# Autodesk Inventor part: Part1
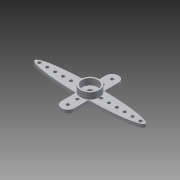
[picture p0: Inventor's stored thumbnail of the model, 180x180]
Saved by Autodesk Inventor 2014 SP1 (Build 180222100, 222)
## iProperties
Created: 2017-05
Part Number: Part1
Material: PVC-Piping
Document SubType Name: Modeling
Designer: L.Đ.P
Density: 1.4 g/cm^3
Appearance: Smooth - White
Author: L.Đ.P
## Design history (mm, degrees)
sketch "Sketch1" dims "d0" = 17.5
  geometry: L1 (0, 0)-(0, -2.5); 1 further point; 1 other entity
  constraints: 2 end point, 1 coincident, 1 vertical, 1 vertical alignment, 2 other
  dimensions: "d1" = 2.5 distance of L1.start L1.end
extrude "Extrusion1" new body sketch "Sketch1" stored distance "d2" = 1; taper "d3" = 0 deg
sketch "Sketch2"
  geometry: C1 r 3 at (0, 0); 1 further point; 1 other entity
  constraints: 1 centre point, 1 coincident, 1 other
  dimensions: "d4" = 6 diameter of C1
extrude "Extrusion2" join sketch "Sketch2" distance "d5" = 2; taper "d6" = 0 deg; dims "d23" = 1, "d24" = 0
sketch "Sketch3"
  geometry: C1 r 3 at (0, 0) reference; C2 r 2.5 at (0, 0)
  constraints: 1 centre point, 1 coincident
  dimensions: "d7" = 5 diameter of C2
extrude "Extrusion3" cut sketch "Sketch3" distance "d8" = 2; taper "d9" = 0 deg
sketch "Sketch4"
  geometry: C1 r 2 at (0, 0); 1 further point; 1 other entity
  constraints: 1 centre point, 1 coincident, 1 other
  dimensions: "d10" = 4 diameter of C1
extrude "Extrusion4" cut sketch "Sketch4" distance "d11" = 0.5; taper "d12" = 0 deg
sketch "Sketch5"
  geometry: C1 r 2 at (0, 0) reference; C2 r 1 at (0, 0)
  constraints: 1 centre point, 1 coincident
  dimensions: "d13" = 2 diameter of C2
extrude "Extrusion5" cut sketch "Sketch5" stored distance "d14" = 1; taper "d15" = 0 deg
sketch "Sketch6"
  geometry: L1 (0, 0)-(0, -1.269); L2 (0, 0)-(-1.481, 0); C1 r 0.5 at (-16, 0); 1 other entity
  constraints: 4 end point, 1 centre point, 1 perpendicular, 1 point on line, 1 vertical, 1 other
  dimensions: "d16" = 1 diameter of C1; "d17" = 16 distance of L1.start C1.centre
extrude "Extrusion6" cut sketch "Sketch6" stored distance "d18" = 1; taper "d19" = 0 deg
pattern_linear "Rectangular Pattern1" dims "d22" = 2.5
mirror "Mirror2"
sketch "Sketch7"
  geometry: L1 (2, -7)-(-2, -7); L2 (-2, -7)-(-2, 7); L3 (-2, 7)-(2, 7); L4 (2, 7)-(2, -7); L5 (0, 0)-(0, 1.479); L6 (0, 0)-(-1.001, 0); C1 r 2 at (0, 0) reference; C2 r 2 at (0, 0); A1 r 3 centre (0, 0) between (1.675, 2.489) and (-1.675, 2.489) reference; 4 further points
  constraints: 12 end point, 3 midpoint, 3 parallel, 2 coincident, 2 horizontal alignment, 2 perpendicular, 2 point on line, 1 centre point, 1 concentric, 1 horizontal, 4 other
  dimensions: "d25" = 4 distance of L2.end L3.end; "d26" = 14 distance of L1.end L2.end
extrude "Extrusion7" join sketch "Sketch7" distance "d27" = 1; taper "d28" = 0 deg
sketch "Sketch8"
  geometry: C1 r 0.5 at (0, 7); A1 r 2 centre (0, 7) between (2, 7) and (-2, 7) reference
  constraints: 1 centre point, 1 coincident
  dimensions: "d29" = 1 diameter of C1
extrude "Extrusion8" cut sketch "Sketch8" distance "d30" = 1; taper "d31" = 0 deg
pattern_linear "Rectangular Pattern2" dims "d34" = 3
mirror "Mirror3"
body "Solid1"
